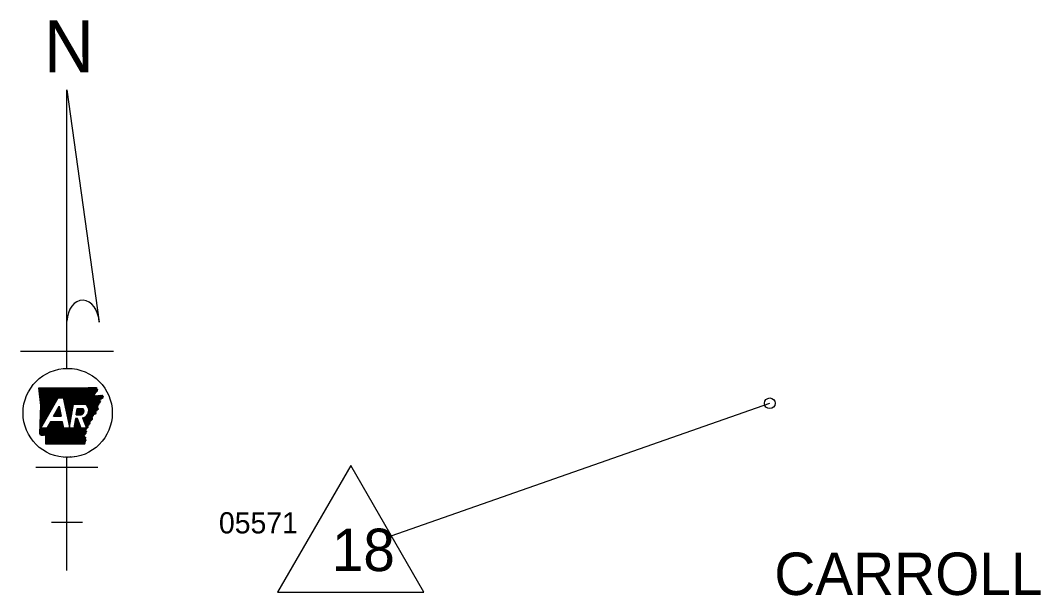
# Model space of a CAD drawing. Extents: x -24122 to 24238, y -8840 to 11381.
# Drawn here: x 10390 to 16157, y 1076 to 4330 of the extents above; entities that cross this region are included whole.
import ezdxf

# ---------------------------------------------------------------- set-up
doc = ezdxf.new("R2010")
doc.units = 0
for name, color, linetype in [('R_Annotation', 7, 'Continuous'), ('R_Border', 7, 'Continuous'), ('R_No Plot', 7, 'Continuous')]:
    doc.layers.add(name, color=color, linetype=linetype)

msp = doc.modelspace()

# ---------------------------------------------------------------- linework, layer by layer
at = {"layer": 'R_Annotation'}
for p, q in [((10653.1, 3937.1), (10834.9, 2623)), ((10653.1, 2361.2), (10653.1, 3937.1)), ((10389.9, 2458.7), (10916.2, 2458.7)), ((10493.4, 2248.4), (10495.6, 2250.5)), ((10494.2, 2242.2), (10502.6, 2250.5)), ((10495, 2236), (10509.5, 2250.5)), ((10495.8, 2229.8), (10516.5, 2250.5)), ((10496.5, 2223.6), (10523.5, 2250.5)), ((10497.3, 2217.4), (10530.4, 2250.5)), ((10498.1, 2211.2), (10537.4, 2250.5)), ((10498.8, 2205), (10544.3, 2250.5)), ((10499.6, 2198.8), (10551.3, 2250.5)), ((10500.4, 2192.6), (10558.3, 2250.5)), ((10501.2, 2186.4), (10565.2, 2250.5)), ((10501.9, 2180.2), (10572.2, 2250.5)), ((10502.7, 2174), (10579.2, 2250.5)), ((10503.5, 2167.8), (10586.1, 2250.5)), ((10503.7, 2098.4), (10655.9, 2250.6)), ((10503.9, 2105.6), (10648.9, 2250.6)), ((10504.2, 2112.8), (10641.9, 2250.6)), ((10504.2, 2161.6), (10593.1, 2250.5)), ((10504.4, 2120), (10635, 2250.6)), ((10504.7, 2127.2), (10628, 2250.5)), ((10504.9, 2134.4), (10621, 2250.5)), ((10505, 2155.4), (10600.1, 2250.5)), ((10505.1, 2141.6), (10614, 2250.5)), ((10505.4, 2148.8), (10607, 2250.5)), ((10607.1, 2194.9), (10662.9, 2250.6)), ((10614.1, 2194.9), (10669.9, 2250.6)), ((10621.1, 2194.9), (10676.9, 2250.7)), ((10628, 2194.9), (10684, 2250.8)), ((10632.4, 2192.3), (10691, 2250.9)), ((10633.6, 2186.5), (10698.1, 2251)), ((10634.8, 2180.8), (10705.2, 2251.1)), ((10636.1, 2175), (10712.3, 2251.2)), ((10637.3, 2169.3), (10719.3, 2251.4)), ((10638.5, 2163.6), (10726.4, 2251.5)), ((10639.7, 2157.8), (10733.5, 2251.6)), ((10641, 2152.1), (10740.6, 2251.7)), ((10642.2, 2146.3), (10747.7, 2251.8)), ((10643.4, 2140.6), (10754.7, 2251.9)), ((10644.7, 2134.9), (10761.8, 2252)), ((10645.9, 2129.1), (10768.9, 2252.1)), ((10647.1, 2123.4), (10776, 2252.3)), ((10648.3, 2117.7), (10783.1, 2252.4)), ((10696.7, 2159.1), (10790.2, 2252.6)), ((10703.7, 2159.1), (10797.4, 2252.8)), ((10710.7, 2159.1), (10804.5, 2252.9)), ((10717.6, 2159.1), (10811.6, 2253.1)), ((10724.6, 2159.1), (10818.8, 2253.2)), ((10505.8, 2023.3), (10602.9, 2194.9)), ((10602.9, 2194.9), (10631.8, 2194.9)), ((10731.6, 2159.1), (10820.3, 2247.8)), ((10738.5, 2159.1), (10823.7, 2244.2)), ((10745.5, 2159.1), (10824.6, 2238.2)), ((10752.5, 2159.1), (10808.7, 2215.3)), ((10758.8, 2158.4), (10807.3, 2207)), ((10762.6, 2155.3), (10814.7, 2207.3)), ((10766, 2151.7), (10822, 2207.7)), ((10769, 2147.8), (10829.3, 2208.1)), ((10771.6, 2143.4), (10836.7, 2208.5)), ((10773.7, 2138.5), (10844, 2208.9)), ((10775.3, 2133.2), (10850.6, 2208.5)), ((10776.3, 2127.2), (10853.9, 2204.8)), ((10850.8, 2194.7), (10857.1, 2201.1)), ((10502.7, 2069.6), (10570.2, 2137)), ((10503, 2076.8), (10579.3, 2153.1)), ((10503.2, 2084), (10588.4, 2169.1)), ((10503.5, 2091.2), (10597.5, 2185.2)), ((10577.3, 2090.6), (10609, 2146.8)), ((10595, 2122), (10610.9, 2137.9)), ((10604.1, 2138), (10609.7, 2143.6)), ((10649.6, 2111.9), (10689.1, 2151.4)), ((10650.8, 2106.2), (10687.6, 2143)), ((10652, 2100.4), (10686.2, 2134.6)), ((10690.4, 2159.1), (10757.9, 2159.1)), ((10705.1, 2098.2), (10741.8, 2134.9)), ((10706.5, 2106.6), (10734.8, 2134.9)), ((10708, 2115), (10727.8, 2134.9)), ((10709.5, 2123.5), (10720.9, 2134.9)), ((10710.9, 2131.9), (10713.9, 2134.9)), ((10711.5, 2134.9), (10743.1, 2134.9)), ((10746.1, 2069.1), (10823.3, 2146.3)), ((10748, 2064), (10824.6, 2140.7)), ((10749.8, 2058.9), (10825.9, 2135)), ((10768.8, 2098.8), (10822, 2152)), ((10774.8, 2111.8), (10838.1, 2175)), ((10776.3, 2120.2), (10837.3, 2181.2)), ((10830.3, 2160.3), (10838.9, 2168.9)), ((12486.6, 1414.9), (14625.7, 2163.7)), ((10502, 2048), (10542.9, 2088.8)), ((10502.3, 2055.2), (10552, 2104.9)), ((10502.5, 2062.4), (10561.1, 2121)), ((10577.3, 2090.6), (10621, 2090.6)), ((10577.6, 2090.6), (10613.4, 2126.4)), ((10584.6, 2090.6), (10614.6, 2120.7)), ((10585.9, 2105.9), (10612.2, 2132.2)), ((10591.5, 2090.6), (10615.8, 2115)), ((10598.5, 2090.6), (10617.1, 2109.2)), ((10605.5, 2090.6), (10618.3, 2103.5)), ((10612.4, 2090.6), (10619.5, 2097.7)), ((10619.4, 2090.6), (10620.8, 2092)), ((10653.3, 2094.7), (10684.7, 2126.1)), ((10654.5, 2089), (10683.2, 2117.7)), ((10655.7, 2083.2), (10681.7, 2109.3)), ((10656.9, 2077.5), (10680.3, 2100.8)), ((10658.2, 2071.8), (10678.8, 2092.4)), ((10659.4, 2066), (10677.3, 2084)), ((10699.1, 2063.9), (10713, 2077.9)), ((10700.6, 2072.4), (10706.1, 2077.9)), ((10713.2, 2077.9), (10701.5, 2077.9)), ((10705.1, 2098.2), (10734, 2098.2)), ((10712.1, 2098.2), (10745.6, 2131.8)), ((10733.4, 2023.3), (10713.2, 2077.9)), ((10719, 2098.2), (10748, 2127.2)), ((10726, 2098.2), (10749.3, 2121.5)), ((10733, 2098.2), (10748.7, 2113.9)), ((10741.8, 2080.8), (10763, 2023.3)), ((10742.3, 2079.3), (10744.4, 2081.4)), ((10744.2, 2074.2), (10757.5, 2087.5)), ((10751.7, 2053.9), (10827.2, 2129.4)), ((10753.6, 2048.8), (10795.4, 2090.6)), ((10755.5, 2043.7), (10794.6, 2082.8)), ((10803.4, 2098.6), (10813.2, 2108.3)), ((10500.2, 1990.4), (10533.1, 2023.3)), ((10500.4, 1997.5), (10526.1, 2023.3)), ((10500.6, 2004.7), (10519.1, 2023.3)), ((10500.8, 2011.9), (10512.2, 2023.3)), ((10501.1, 2019.2), (10506.5, 2024.6)), ((10501.3, 2026.4), (10515.6, 2040.7)), ((10501.6, 2033.6), (10524.7, 2056.7)), ((10501.8, 2040.8), (10533.8, 2072.8)), ((10502.8, 1986.1), (10576, 2059.3)), ((10539.1, 2023.3), (10505.8, 2023.3)), ((10507, 1983.2), (10583, 2059.3)), ((10512, 1981.3), (10590, 2059.3)), ((10520.2, 1982.6), (10596.9, 2059.3)), ((10527.3, 1982.7), (10603.9, 2059.3)), ((10532.8, 1981.2), (10610.9, 2059.3)), ((10533, 1967.5), (10624.8, 2059.3)), ((10533, 1974.5), (10617.8, 2059.3)), ((10533, 1960.6), (10628.5, 2056)), ((10533.1, 1953.6), (10629.7, 2050.2)), ((10533.1, 1946.7), (10630.9, 2044.5)), ((10533.1, 1939.7), (10632.1, 2038.8)), ((10533.2, 1932.9), (10633.4, 2033)), ((10559.5, 2059.3), (10539.1, 2023.3)), ((10540.2, 1932.9), (10634.6, 2027.3)), ((10547, 2037.2), (10569.1, 2059.3)), ((10547.1, 1932.8), (10637.5, 2023.3)), ((10554.1, 1932.8), (10644.5, 2023.3)), ((10556.1, 2053.3), (10562.1, 2059.3)), ((10627.8, 2059.3), (10559.5, 2059.3)), ((10561, 1932.8), (10651.5, 2023.3)), ((10568, 1932.8), (10658.4, 2023.3)), ((10574.9, 1932.8), (10665.4, 2023.3)), ((10581.9, 1932.8), (10672.4, 2023.3)), ((10588.8, 1932.8), (10679.3, 2023.3)), ((10595.8, 1932.8), (10686.3, 2023.3)), ((10602.8, 1932.8), (10722.6, 2052.6)), ((10609.7, 1932.7), (10724.4, 2047.5)), ((10616.7, 1932.7), (10726.3, 2042.4)), ((10623.6, 1932.7), (10728.2, 2037.3)), ((10630.6, 1932.7), (10730.1, 2032.2)), ((10692, 2023.3), (10635.5, 2023.3)), ((10637.5, 1932.7), (10732, 2027.1)), ((10644.5, 1932.7), (10735.1, 2023.3)), ((10651.4, 1932.7), (10742, 2023.3)), ((10658.4, 1932.7), (10749, 2023.3)), ((10660.6, 2060.3), (10675.9, 2075.5)), ((10661.8, 2054.5), (10674.4, 2067.1)), ((10663.1, 2048.8), (10672.9, 2058.7)), ((10664.3, 2043.1), (10671.5, 2050.2)), ((10665.3, 1932.7), (10756, 2023.3)), ((10665.5, 2037.3), (10670, 2041.8)), ((10666.8, 2031.6), (10668.5, 2033.3)), ((10672.3, 1932.6), (10758.3, 2018.6)), ((10693.2, 2030.2), (10720.7, 2057.7)), ((10694.7, 2038.6), (10718.8, 2062.7)), ((10696.2, 2047.1), (10716.9, 2067.8)), ((10697.6, 2055.5), (10715, 2072.9)), ((10763, 2023.3), (10733.4, 2023.3)), ((10757.4, 2038.6), (10793.8, 2075.1)), ((10759.2, 2033.5), (10780.6, 2054.9)), ((10761.1, 2028.4), (10777.6, 2044.9)), ((10679.3, 1932.6), (10758.6, 2012)), ((10686.2, 1932.6), (10758.9, 2005.3)), ((10693.2, 1932.6), (10759.2, 1998.7)), ((10700.1, 1932.6), (10747.8, 1980.3)), ((10707.1, 1932.6), (10749.9, 1975.5)), ((10714, 1932.6), (10752.1, 1970.6)), ((10721, 1932.6), (10754.2, 1965.8)), ((10727.9, 1932.6), (10756.4, 1961)), ((10734.9, 1932.5), (10758.2, 1955.8)), ((10741.8, 1932.5), (10755, 1945.7)), ((10748.8, 1932.5), (10751.9, 1935.6)), ((10653.1, 1217.6), (10653.1, 1857.1)), ((10477.7, 1802.8), (10828.5, 1802.8)), ((10565.3, 1491.2), (10740.8, 1491.2)), ((11844.1, 1096.1), (12670.7, 1096.1))]:
    msp.add_line(p, q, dxfattribs=at)
for points in [[(10493.2, 2250.5), (10589.3, 2250.5), (10673.6, 2250.6), (10773.1, 2252.2), (10819.2, 2253.3)], [(10493.2, 2250.5), (10589.3, 2250.5), (10673.6, 2250.6), (10773.1, 2252.2), (10819.2, 2253.3)], [(10503.8, 2101.1), (10505.5, 2151.8), (10493.2, 2250.5)], [(10500.1, 1990.5), (10505.5, 2151.8), (10493.2, 2250.5)], [(10631.8, 2194.9), (10667.6, 2027.9), (10690.4, 2159.1)], [(10849.4, 2209.1), (10857.7, 2200.4), (10837, 2183.4), (10839.2, 2166.2), (10821.4, 2154.4), (10827.5, 2128), (10813.8, 2115.5), (10812.6, 2101.9), (10795.9, 2095.9), (10793.3, 2070.2), (10781.4, 2057.4), (10775.6, 2038.1), (10758.1, 2022.1), (10759.5, 1994), (10747.6, 1980.7), (10758.4, 1956.5), (10750.9, 1932.5)], [(10804.9, 2206.8), (10850.1, 2209.2)], [(10805, 2206.9), (10850, 2209.1)], [(10609, 2146.8), (10621, 2090.6)], [(10705.1, 2098.2), (10711.5, 2134.9)], [(10500.1, 1990.5), (10503.8, 2101.1)], [(10701.5, 2077.9), (10692, 2023.3)], [(10635.5, 2023.3), (10627.8, 2059.3)], [(10750.9, 1932.5), (10533.1, 1932.9), (10533, 1981)], [(10750.9, 1932.5), (10533.1, 1932.9), (10533, 1981)], [(12670.7, 1096.1), (12257.4, 1811.9), (11844.1, 1096.1)]]:
    msp.add_lwpolyline(points, dxfattribs=at)
msp.add_circle((14625.7, 2163.7), 30.2, dxfattribs=at)
for centre, major_axis, ratio, start_param, end_param in [((10743.9, 2620.1), (-3.9, 126.3), 0.719778, 4.712385, 7.768526), ((10727.1, 2119.4), (-22.3, 0), 0.999987, 1.887169, 3.90762), ((10732.8, 2123.4), (-43.6, 0), 0.999987, 1.777838, 4.099264)]:
    msp.add_ellipse(centre, major_axis=major_axis, ratio=ratio, start_param=start_param, end_param=end_param, dxfattribs=at)
msp.add_ellipse((10657.2, 2109.2), major_axis=(252.1, 0), ratio=0.999976, dxfattribs=at)
for points in [[(10819.2, 2253.3), (10819.5, 2250.6), (10820.3, 2249.3), (10820.4, 2246.8), (10821.5, 2245.7), (10823.2, 2244.6), (10824.7, 2242.9), (10825.1, 2240.9), (10824.6, 2238.8), (10824.5, 2236.5), (10824.3, 2234.4), (10823.9, 2232.7), (10822.5, 2231.1), (10821.1, 2230.1), (10819.9, 2228.9), (10819, 2227.5), (10817.4, 2226.1), (10815.9, 2224.6), (10814.6, 2223.3), (10813.4, 2221.6), (10812.8, 2219.8), (10811.4, 2218.5), (10810.3, 2217.3), (10808.9, 2215.7), (10808.2, 2214.1), (10806.9, 2212.3), (10806.5, 2210.5), (10805.7, 2209.1), (10805.6, 2208.8)], [(10819.2, 2253.3), (10819.5, 2250.6), (10820.3, 2249.3), (10820.5, 2246.8), (10821.5, 2245.7), (10823.2, 2244.6), (10824.7, 2242.9), (10825.1, 2240.9), (10824.6, 2238.8), (10824.5, 2236.5), (10824.3, 2234.5), (10823.9, 2232.6), (10822.5, 2231.2), (10821.1, 2230.1), (10819.9, 2228.8), (10819, 2227.5), (10817.4, 2226.1), (10815.9, 2224.6), (10814.6, 2223.3), (10813.4, 2221.6), (10812.8, 2219.8), (10811.4, 2218.5), (10810.4, 2217.3), (10808.9, 2215.7), (10808.2, 2214.1), (10806.8, 2212.3), (10806.5, 2210.5), (10805.7, 2209), (10805.6, 2208.8)], [(10849.4, 2209.1), (10850, 2209.1), (10852.1, 2207), (10852.9, 2205.2), (10854.3, 2204.2), (10855.8, 2203.7), (10856.9, 2202.3), (10857.7, 2200.8), (10857.3, 2199.5), (10855.6, 2199.4), (10853.7, 2199.1), (10852, 2199.2), (10850.5, 2197.9), (10851.8, 2196.4), (10853.6, 2194.9), (10854, 2193.3), (10853.1, 2191.8), (10851.2, 2190.9), (10849.3, 2190.2), (10847.7, 2188.8), (10846.9, 2187.4), (10845.1, 2186.8), (10843.2, 2186.3), (10841.5, 2186.1), (10839.6, 2185.7), (10837.8, 2184.8), (10837, 2183.3), (10837.2, 2181.1), (10837.2, 2178.8), (10839.1, 2178), (10840.8, 2177.9), (10842.5, 2177.1), (10842.3, 2175.8), (10841.1, 2174.1), (10839.6, 2172.8), (10838.1, 2172.1), (10836.7, 2170.9), (10837.2, 2169.6), (10838.5, 2168.8), (10839.4, 2167.4), (10839.2, 2166.2), (10837.8, 2165.3), (10836.3, 2165.7), (10835.1, 2167.2), (10833.8, 2167.6), (10832.7, 2168.2), (10831.4, 2167.4), (10831.4, 2165.7), (10830.9, 2163.8), (10831.3, 2162.5), (10831.8, 2160.6), (10831.8, 2159.1), (10831.3, 2157.1), (10830.3, 2155), (10829.2, 2154.4), (10828.6, 2156.6), (10828.4, 2158.5), (10827.7, 2159.6), (10826.7, 2159.6), (10825.5, 2158.7), (10824.1, 2157.3), (10822.4, 2155.8), (10821.4, 2154.4), (10822, 2152.5), (10823.2, 2152.1), (10824.3, 2152.4), (10824.8, 2153.6), (10825.7, 2153.8), (10826.7, 2151.9)], [(10826.7, 2151.9), (10827, 2150.2), (10826, 2148.4), (10825.6, 2146.5), (10825.7, 2144.7), (10823.9, 2143.7), (10822.2, 2142.5), (10823.2, 2141), (10825, 2139.7), (10826.7, 2138.8), (10827.8, 2137.7), (10828.2, 2135.3), (10828.5, 2133.7), (10829.1, 2131.6), (10829.3, 2130.1), (10828.2, 2128.3), (10827, 2128), (10825.7, 2128.4), (10824.1, 2128.5), (10822.9, 2127.4), (10822, 2125.7), (10821.1, 2124), (10820.4, 2122.6), (10819.8, 2121), (10818.5, 2119.2), (10816.9, 2119), (10815, 2118.5), (10813.8, 2117.2), (10814.1, 2115), (10815.1, 2113.5), (10815.9, 2111.7), (10816.5, 2110), (10816.3, 2108), (10815.4, 2106.5), (10814.3, 2105.6), (10813.8, 2103.7), (10813.1, 2102.3), (10812.4, 2101.8), (10810.9, 2101.9), (10809.4, 2102.2), (10808.1, 2102.1), (10806.9, 2101.5), (10805.6, 2101.9), (10804.3, 2103.3), (10803.2, 2104.4), (10802, 2104.8), (10800.8, 2104.1), (10800.6, 2102.2), (10801.2, 2100.2), (10801.7, 2097.4), (10801.2, 2095.8), (10801, 2093)], [(10801, 2093), (10798.9, 2091.5), (10797.9, 2089.8), (10792.7, 2090.3), (10792.8, 2088.4), (10790.9, 2087.4), (10789.3, 2086.2), (10790.2, 2084.8), (10792, 2083.5), (10793.8, 2082.5), (10794.9, 2081.5), (10795.2, 2079), (10795.5, 2077.5), (10796.1, 2075.3), (10796.3, 2073.9), (10795.3, 2072.1), (10794, 2071.7), (10792.7, 2072.2), (10791.2, 2072.3), (10789.9, 2071.1), (10789, 2069.4), (10788.2, 2067.7), (10787.5, 2066.3), (10786.8, 2064.8), (10785.5, 2063), (10783.9, 2062.7), (10782, 2062.2), (10780.9, 2061), (10781.1, 2058.7), (10782.1, 2057.3), (10783, 2055.4), (10783.5, 2053.8), (10783.3, 2051.8), (10782.5, 2050.3), (10781.4, 2049.4), (10780.9, 2047.5), (10780.1, 2046), (10779.4, 2045.6), (10778, 2045.7), (10776.5, 2046), (10775.1, 2045.9), (10773.9, 2045.2), (10772.6, 2045.7), (10771.3, 2047.1), (10770.2, 2048.2), (10769.1, 2048.6), (10767.8, 2047.9), (10767.6, 2045.9), (10768.2, 2043.9), (10768.7, 2041.2), (10768.2, 2039.6), (10768, 2036.8)], [(10768, 2036.8), (10767.9, 2036.7), (10766.8, 2035.3), (10767.4, 2033.2), (10769.7, 2032.4), (10770.8, 2030.4), (10770.8, 2028.6), (10770.1, 2026.2), (10769, 2025), (10766.9, 2024.6), (10765.3, 2024.3), (10765.1, 2021.5), (10764.3, 2020.2), (10763.1, 2019.8), (10761.3, 2020.7), (10760.2, 2021.1), (10758.9, 2021.7), (10757.3, 2022.6), (10756, 2022.5), (10756.4, 2019.9), (10756.5, 2019.8), (10757.9, 2017.8), (10759.3, 2016.2), (10760, 2014.4)], [(10768, 2036.8), (10767.9, 2036.7), (10766.8, 2035.3), (10767.4, 2033.2), (10769.7, 2032.4), (10770.8, 2030.4), (10770.8, 2028.6), (10770.1, 2026.2), (10769, 2025), (10766.9, 2024.6), (10765.3, 2024.3), (10765.1, 2021.5), (10764.3, 2020.2), (10763.1, 2019.8), (10761.3, 2020.7), (10760.2, 2021.1), (10758.9, 2021.7), (10757.3, 2022.6), (10756, 2022.5), (10756.4, 2019.9), (10756.5, 2019.8), (10757.9, 2017.8), (10759.3, 2016.2), (10760, 2014.4)], [(10533, 1981), (10533.2, 1980.8), (10532.1, 1981.6), (10530.6, 1982.4), (10528.8, 1982.5), (10526.6, 1982.8), (10524.8, 1983), (10522.9, 1984.2), (10520.9, 1982.9), (10518.6, 1982), (10517.3, 1983.1), (10515.6, 1982.3), (10514.4, 1982.7), (10512.3, 1981.2), (10510.3, 1981.8), (10508.9, 1981.4), (10507.2, 1981.4), (10506.8, 1983.5), (10505, 1983.7), (10503.6, 1984.6), (10502.6, 1986.6), (10501.8, 1988.3), (10500.1, 1990.5)], [(10533, 1981), (10533.2, 1980.8), (10532.1, 1981.6), (10530.6, 1982.4), (10528.8, 1982.5), (10526.6, 1982.8), (10524.8, 1983), (10522.9, 1984.2), (10520.9, 1982.9), (10518.6, 1982), (10517.3, 1983), (10515.6, 1982.3), (10514.4, 1982.7), (10512.3, 1981.2), (10510.3, 1981.8), (10508.9, 1981.4), (10507.1, 1981.4), (10506.8, 1983.4), (10505.1, 1983.7), (10503.6, 1984.6), (10502.6, 1986.7), (10501.8, 1988.3), (10500.1, 1990.5)], [(10760, 2014.4), (10759.4, 2013), (10758.7, 2010.7), (10758.9, 2008.7), (10759.9, 2006.9), (10761.2, 2006), (10762.8, 2004.6), (10762.7, 2002.5), (10761.8, 2001.8), (10759.7, 2002.3), (10758.1, 2003), (10756.7, 2002.6), (10754.9, 2001.7), (10753.5, 2001.5), (10753.6, 1998.6), (10755.4, 1996.6), (10757, 1996.6), (10758.9, 1996.4), (10759.5, 1994.3), (10758.5, 1992.5), (10756.7, 1991.6), (10754.4, 1992.7), (10752.8, 1993.8), (10751.2, 1994.9), (10749.2, 1995.4), (10748.1, 1995.2), (10747.5, 1992.7), (10748.5, 1990.4), (10750, 1988.8), (10751.4, 1986.8), (10751.2, 1985.3), (10750.2, 1984.9), (10748.2, 1984.5), (10747.1, 1983.9), (10746.8, 1983.5), (10747.4, 1981.4), (10747.9, 1979.2), (10747.9, 1977.5), (10747.3, 1976.1), (10746.3, 1973.7), (10746.4, 1972.1), (10747.1, 1971.4), (10748, 1971.6), (10749.2, 1972.4), (10750, 1973.4), (10750.6, 1974.6), (10751.9, 1975.6), (10753.4, 1974.7), (10753.8, 1972.9), (10752.9, 1971.3), (10751.6, 1970.5), (10750.1, 1969.9), (10749, 1968.7), (10749.2, 1967.1), (10750.2, 1966.3), (10752.4, 1966.7), (10753.8, 1967.4), (10754.7, 1968.1), (10755.7, 1969.2), (10756.2, 1970.2), (10757, 1971.3), (10758.4, 1971.6), (10759, 1970.7), (10758.7, 1968.7), (10757.9, 1966.7), (10756.8, 1965.1), (10755.6, 1964), (10754, 1961.6), (10754.3, 1959.3), (10754.9, 1957.4), (10755.7, 1956.1), (10757.2, 1956.3), (10758.7, 1956.5), (10759.7, 1955.8), (10759.6, 1954.1), (10758.4, 1952.4), (10757.3, 1950.9), (10756.7, 1948.8), (10756.9, 1947.3), (10756.9, 1946), (10756.5, 1944.4), (10755.6, 1943.6), (10753.4, 1943.6), (10751.1, 1943.9), (10749.9, 1943.2), (10750.1, 1941.2), (10751.4, 1939.7), (10752.4, 1938.9), (10753.8, 1937.3), (10754.4, 1935.9), (10754.2, 1934.7), (10753.3, 1933.7), (10750.9, 1932.5)], [(10760, 2014.4), (10759.4, 2013), (10758.7, 2010.7), (10758.9, 2008.7), (10759.9, 2006.9), (10761.2, 2006), (10762.8, 2004.6), (10762.7, 2002.5), (10761.8, 2001.8), (10759.7, 2002.3), (10758.1, 2003), (10756.7, 2002.6), (10754.9, 2001.7), (10753.5, 2001.5), (10753.6, 1998.6), (10755.4, 1996.6), (10757, 1996.6), (10758.9, 1996.4), (10759.5, 1994.3), (10758.5, 1992.5), (10756.7, 1991.6), (10754.4, 1992.7), (10752.8, 1993.8), (10751.2, 1994.9), (10749.2, 1995.4), (10748.1, 1995.2), (10747.5, 1992.7), (10748.5, 1990.4), (10750, 1988.8), (10751.4, 1986.8), (10751.2, 1985.3), (10750.2, 1984.9), (10748.2, 1984.5), (10747.1, 1983.9), (10746.8, 1983.5), (10747.4, 1981.4), (10747.9, 1979.2), (10747.9, 1977.5), (10747.3, 1976.1), (10746.3, 1973.7), (10746.4, 1972.1), (10747.1, 1971.4), (10748, 1971.6), (10749.2, 1972.4), (10750, 1973.4), (10750.6, 1974.6), (10751.9, 1975.6), (10753.4, 1974.7), (10753.8, 1972.9), (10752.9, 1971.3), (10751.6, 1970.5), (10750.1, 1969.9), (10749, 1968.7), (10749.2, 1967.1), (10750.2, 1966.3), (10752.4, 1966.7), (10753.8, 1967.4), (10754.7, 1968.1), (10755.7, 1969.2), (10756.2, 1970.2), (10757, 1971.3), (10758.4, 1971.6), (10759, 1970.7), (10758.7, 1968.7), (10757.9, 1966.7), (10756.8, 1965.1), (10755.6, 1964), (10754, 1961.6), (10754.3, 1959.3), (10754.9, 1957.4), (10755.7, 1956.1), (10757.2, 1956.3), (10758.7, 1956.5), (10759.7, 1955.8), (10759.6, 1954.1), (10758.4, 1952.4), (10757.3, 1950.9), (10756.7, 1948.8), (10756.9, 1947.3), (10756.9, 1946), (10756.5, 1944.4), (10755.6, 1943.6), (10753.4, 1943.6), (10751.1, 1943.9), (10749.9, 1943.2), (10750.1, 1941.2), (10751.4, 1939.7), (10752.4, 1938.9), (10753.8, 1937.3), (10754.4, 1935.9), (10754.2, 1934.7), (10753.3, 1933.7), (10750.9, 1932.5)]]:
    msp.add_spline(points, degree=3, dxfattribs=at)

# ---------------------------------------------------------------- texts
for s, height, p in [('N', 293.3, (10522.3, 4036.3)), ('STS 10-03-17', 7.288, (10633.1, 1859.2)), ('18', 240, (12149.7, 1214.7))]:
    msp.add_text(s, height=height, dxfattribs=at).set_placement(p)
at = {"layer": 'R_Border'}
msp.add_text('CARROLL', height=240, dxfattribs=at).set_placement((14651.3, 1079.4))
at = {"layer": 'R_No Plot'}
msp.add_text('05571', height=120, dxfattribs=at).set_placement((11512.1, 1427.7))

doc.saveas('drawing.dxf')
